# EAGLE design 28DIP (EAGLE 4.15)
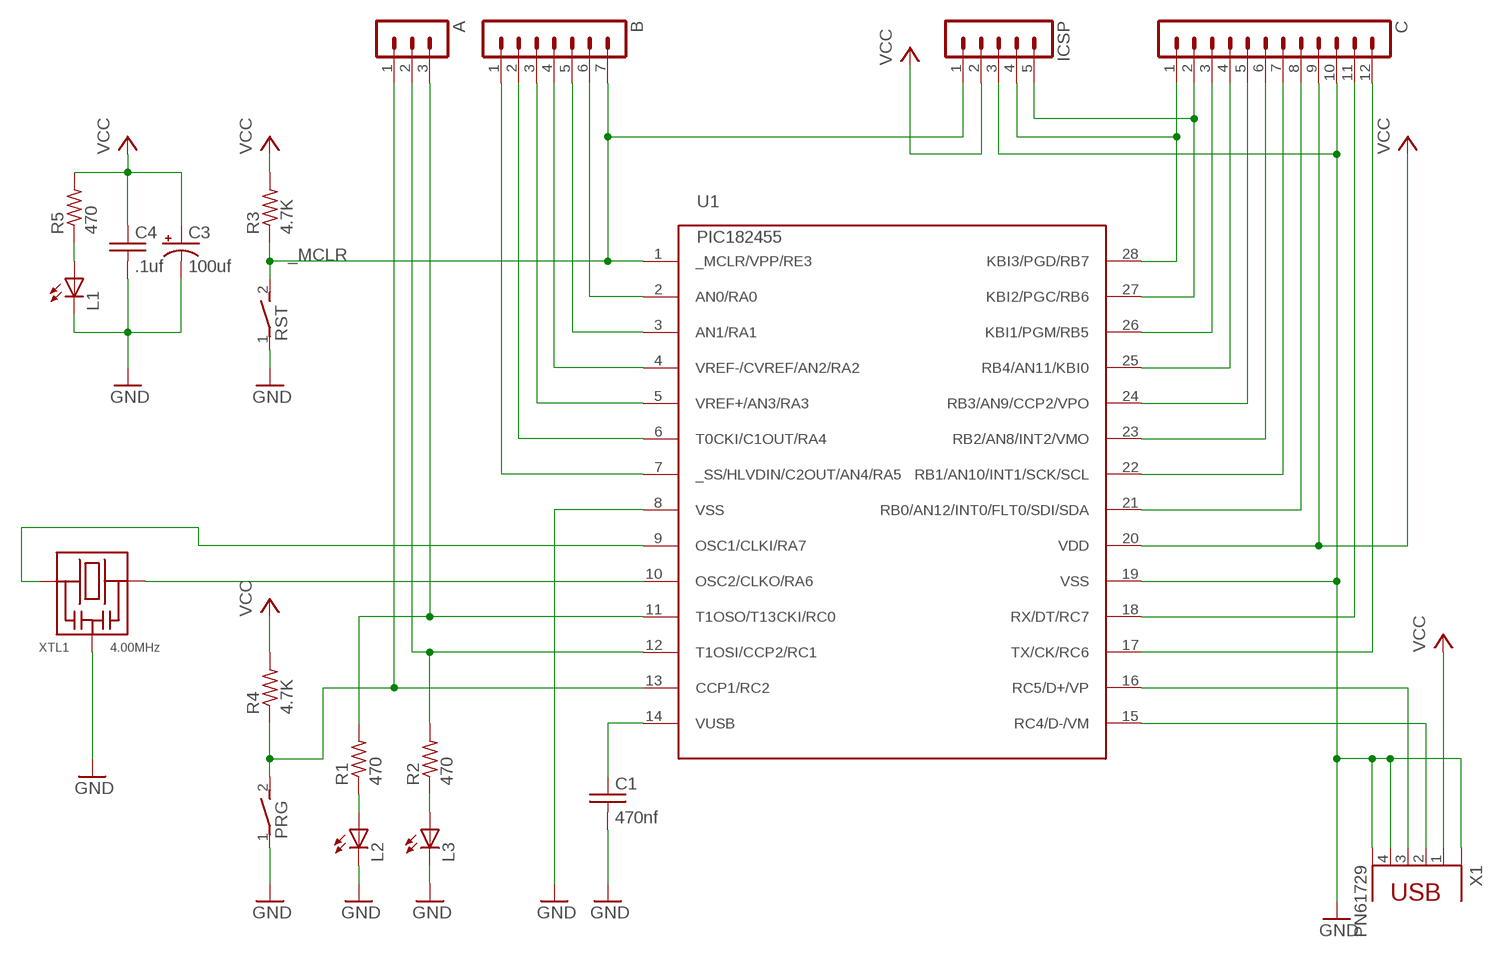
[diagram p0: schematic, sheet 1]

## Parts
A  MA03-1  [MA03-1]
B  MA07-1  [MA07-1]
C  MA12-1  [MA12-1]
C1  470nf  CAPCAP_0200  [CAP_0200]
C3  100uf  CAP_ELECTROLYTICCAP_0200ELECTROLYTIC_0250  [CAP_0200ELECTROLYTIC_0250]
C4  .1uf  CAPCAP_0100  [CAP_0100]
ICSP  MA05-1  [MA05-1]
L1  LED  [LED5MM]
L2  LED  [LED5MM]
L3  LED  [LED5MM]
PRG  SWITCH  [SWITCH]
R1  470  RESISTORRESISTOR_0200FLAT  [RESISTOR_0200FLAT]
R2  470  RESISTORRESISTOR_0200FLAT  [RESISTOR_0200FLAT]
R3  4.7K  RESISTORRESISTOR_0100UP  [RESISTOR_0100UP]
R4  4.7K  RESISTORRESISTOR_0400FLAT  [RESISTOR_0400FLAT]
R5  470  RESISTORRESISTOR_0200FLAT  [RESISTOR_0200FLAT]
RST  SWITCH  [SWITCH]
U1  PIC182455  [DIL28-3]
X1  PN61729  [PN61729]
XTL1  4.00MHz  RESONATOR  [RESONATOR]

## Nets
_MCLR: B.7 ICSP.1 R3.1 RST.2 U1.1(_MCLR/VPP/RE3)
GND: C1.2 C3.- C4.2 C.10 ICSP.3 L1.K(C) L2.K(C) L3.K(C) PRG.1 RST.1 U1.8(VSS) U1.19(VSS) X1.4 X1.GND1(G1) X1.GND2(G2) XTL1.P$1(GND)
N$1: U1.16(RC5/D+/VP) X1.3
N$4: U1.15(RC4/D-/VM) X1.2
N$5: C1.1 U1.14(VUSB)
N$6: L2.A R1.1
N$7: A.1 PRG.2 R4.1 U1.13(CCP1/RC2)
N$8: L3.A R2.1
N$9: L1.A R5.1
N$10: A.3 R1.2 U1.11(T1OSO/T13CKI/RC0)
N$11: A.2 R2.2 U1.12(T1OSI/CCP2/RC1)
N$12: C.1 ICSP.4 U1.28(KBI3/PGD/RB7)
N$13: C.2 ICSP.5 U1.27(KBI2/PGC/RB6)
N$14: C.3 U1.26(KBI1/PGM/RB5)
N$15: C.4 U1.25(RB4/AN11/KBI0)
N$16: C.5 U1.24(RB3/AN9/CCP2/VPO)
N$17: C.6 U1.23(RB2/AN8/INT2/VMO)
N$18: C.7 U1.22(RB1/AN10/INT1/SCK/SCL)
N$19: C.8 U1.21(RB0/AN12/INT0/FLT0/SDI/SDA)
N$20: B.6 U1.2(AN0/RA0)
N$21: B.5 U1.3(AN1/RA1)
N$22: B.4 U1.4(VREF-/CVREF/AN2/RA2)
N$23: B.3 U1.5(VREF+/AN3/RA3)
N$24: B.2 U1.6(T0CKI/C1OUT/RA4)
N$25: B.1 U1.7(_SS/HLVDIN/C2OUT/AN4/RA5)
N$26: C.12 U1.17(TX/CK/RC6)
N$27: C.11 U1.18(RX/DT/RC7)
N$28: U1.10(OSC2/CLKO/RA6) XTL1.P$2
N$31: U1.9(OSC1/CLKI/RA7) XTL1.P$3
VCC: C3.+ C4.1 C.9 ICSP.2 R3.2 R4.2 R5.2 U1.20(VDD) X1.1

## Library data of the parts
A = UBW:MA03-1: PIN HEADER
B = UBW:MA07-1: PIN HEADER
C = UBW:MA12-1: PIN HEADER
C1 C4 = UBW:CAP
C3 = UBW:CAP_ELECTROLYTIC
ICSP = UBW:MA05-1: PIN HEADER
L1-L3 = UBW:LED
PRG RST = UBW:SWITCH: DIL/CODE SWITCH
R1-R5 = UBW:RESISTOR
U1 = UBW:PIC18*2455
X1 = UBW:PN61729: BERG USB connector
XTL1 = UBW:RESONATOR

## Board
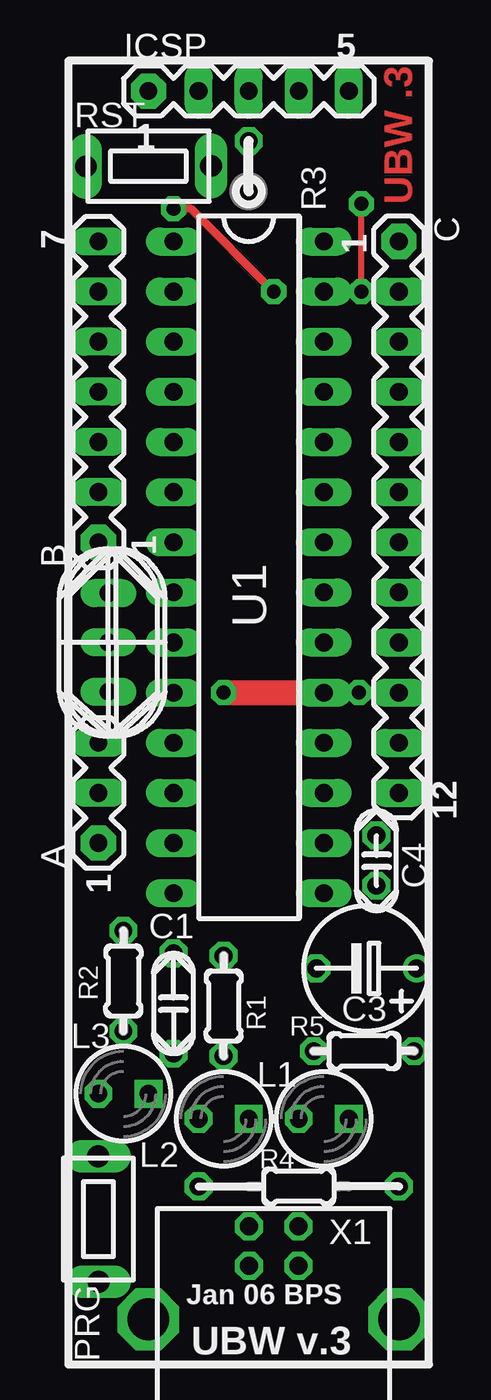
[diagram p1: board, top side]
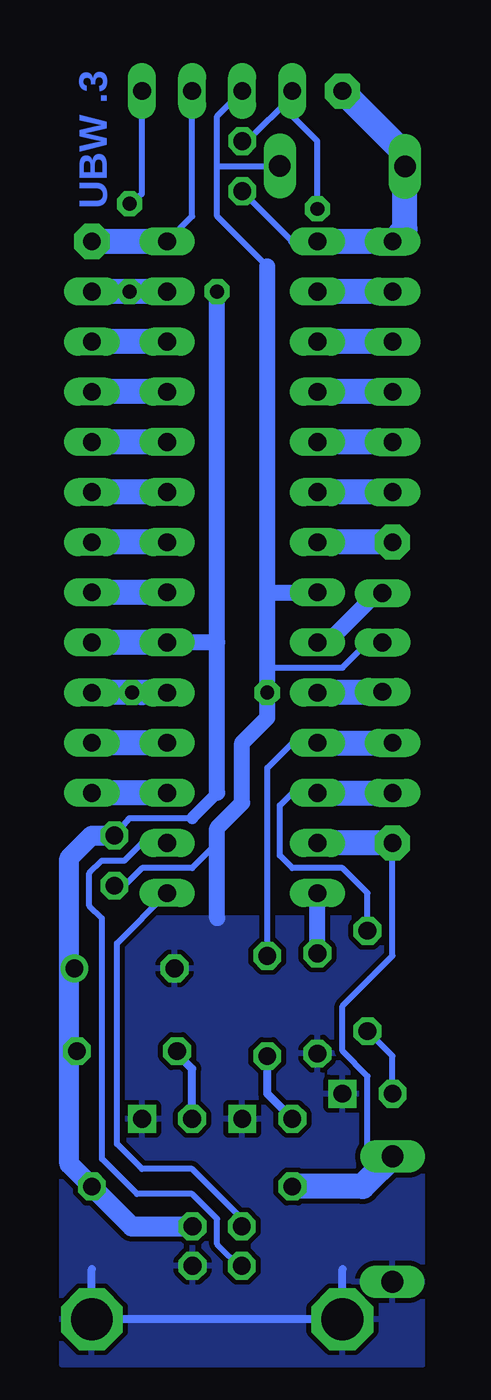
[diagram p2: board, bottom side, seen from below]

No outline drawn. Coordinates in mm, seen from the top.
Copper layers (1*16): Top 0.035mm / dielectric 1.5mm / Bottom 0.035mm
Design rules "New Text Document": minimum track width 10mil, minimum drill 24mil, track to track 10mil, track to pad 10mil, pad to pad 10mil, via to via 10mil, smd to smd 10mil, copper to edge 40mil, drill to drill 10mil, minimum pad ring 10mil, minimum via ring 8mil, stop-mask expansion 0mil, vias tented up to drill 0mil, thermal gap 10mil

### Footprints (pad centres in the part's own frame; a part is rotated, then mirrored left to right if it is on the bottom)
MA03-1 = drill 0.9 pad 1.778 octagon: 1 -2.54,0 | drill 0.9 long: 2 0,0; 3 2.54,0
MA07-1 = drill 0.9 pad 1.778 octagon: 1 -7.62,0 | drill 0.9 long: 2 -5.08,0; 3 -2.54,0; 4 0,0; 5 2.54,0; 6 5.08,0; 7 7.62,0
MA12-1 = drill 0.9 pad 1.778 octagon: 1 -13.97,0 | drill 0.9 long: 2 -11.43,0; 3 -8.89,0; 4 -6.35,0; 5 -3.81,0; 6 -1.27,0; 7 1.27,0; 8 3.81,0; 9 6.35,0; 10 8.89,0; 11 11.43,0; 12 13.97,0
CAP_0200 = drill 0.9 octagon: 1 -2.54,0; 2 2.54,0
CAP_0200ELECTROLYTIC_0250 = drill 0.9 round: + -2.54,0 | drill 0.9 octagon: - 2.54,0
CAP_0100 = drill 0.9 octagon: 1 -1.27,0; 2 1.27,0
MA05-1 = drill 0.9 pad 1.778 octagon: 1 -5.08,0 | drill 0.9 long: 2 -2.54,0; 3 0,0; 4 2.54,0; 5 5.08,0
LED5MM = drill 0.9 octagon: A -1.27,0 | drill 0.9 square: K 1.27,0
SWITCH = drill 1.1 long: 1 0.011,-3.175; 2 -0.011,3.175
RESISTOR_0200FLAT = drill 0.9 octagon: 1 -2.54,0; 2 2.54,0
RESISTOR_0100UP = drill 0.9 octagon: 1 -1.27,0; 2 1.27,0
RESISTOR_0400FLAT = drill 0.9 octagon: 1 -5.08,0; 2 5.08,0
DIL28-3 = drill 0.9 long: 1 -16.51,-3.81; 2 -13.97,-3.81; 3 -11.43,-3.81; 4 -8.89,-3.81; 5 -6.35,-3.81; 6 -3.81,-3.81; 7 -1.27,-3.81; 8 1.27,-3.81; 9 3.81,-3.81; 10 6.35,-3.81; 11 8.89,-3.81; 12 11.43,-3.81; 13 13.97,-3.81; 14 16.51,-3.81; 15 16.51,3.81; 16 13.97,3.81; 17 11.43,3.81; 18 8.89,3.81; 19 6.35,3.81; 20 3.81,3.81; 21 1.27,3.81; 22 -1.27,3.81; 23 -3.81,3.81; 24 -6.35,3.81; 25 -8.89,3.81; 26 -11.43,3.81; 27 -13.97,3.81; 28 -16.51,3.81
PN61729 = drill 0.9 octagon: 1 1.25,4.71; 2 -1.25,4.71; 3 -1.25,2.71; 4 1.25,2.71 | drill 2.108 octagon: GND1 -6.35,0; GND2 6.35,0
RESONATOR = drill 0.9 pad 1.27 long: P$1 0,0; P$2 0,2.5; P$3 0,-2.5

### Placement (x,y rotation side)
A  2.54,29.21 90 top
B  2.54,49.53 90 top
C  17.78,43.18 270 top
C1  6.35,18.54 270 top
C3  16.13,20.32 180 top
C4  16.64,25.78 270 top
ICSP  10.16,64.77 0 top
L1  13.97,12.7 0 top
L2  8.89,12.7 0 top
L3  3.81,13.97 0 top
PRG  2.54,7.62 0 top
R1  8.89,18.41 90 top
R2  3.81,19.68 90 top
R3  10.16,60.96 90 top
R4  12.7,9.27 0 top
R5  16,16.13 0 top
RST  5.08,60.96 90 top
U1  10.16,40.64 270 top
X1  11.43,2.54 0 top
XTL1  3.05,36.83 180 top

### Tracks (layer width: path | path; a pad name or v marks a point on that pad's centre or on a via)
_MCLR
  Bottom 0.305: 7.62,57.15 R3.1
  Bottom 0.406: U1.1 7.62,57.15
  Bottom 1.27: ICSP.1 1.91,61.59 RST.2 1.91,57.78 B.7 U1.1
GND  (via drill 0.7 pad 1.27)
  Top 1.27: v8.89,34.29 U1.19
  Bottom 0.305: 3.81,36.83 5.08,35.56 8.89,35.56 | 11.43,27.43 11.43,26.67 12.7,25.4 15.24,25.4 16.13,24.51 C4.2 | 11.43,60.96 RST.1 | 8.89,55.88 11.43,58.42 11.43,60.96 | 11.43,60.96 11.43,63.5 ICSP.3
  Bottom 0.406: 5.08,5.08 X1.GND1 X1.GND2 17.78,5.08
  Bottom 0.813: 8.89,39.37 8.89,35.56 v8.89,34.29 8.89,33.02 10.16,31.75 10.16,28.7 11.43,27.43 11.43,22.86 | 8.89,39.37 U1.8 | 3.81,36.83 XTL1.P$1 | 8.89,39.37 8.89,55.88
  Bottom 1.27: U1.19 15.24,34.29 | 15.24,34.29 v15.75,34.29 | 15.24,34.29 C.10
  pour Bottom: 1.02,0.25 1.02,22.86 19.3,22.86 19.3,0.25
N$1
  Bottom 0.305: U1.16 15.24,26.67 16.13,25.78 17.27,25.78 17.91,25.15 17.91,23.5 17.27,22.86 17.27,10.67 15.49,8.89 12.7,8.89 11.43,7.62 11.43,6.35 10.18,5.1 | 10.18,5.1 10.16,5.08 | X1.3 10.18,5.1
N$4
  Bottom 0.305: U1.15 16.51,21.59 16.51,11.43 15.24,10.16 12.7,10.16 10.16,7.62 10.18,7.6 X1.2
N$5
  Bottom 0.813: C1.1 U1.14
N$6
  Bottom 0.406: L2.A 8.89,13.97 R1.1
N$7
  Bottom 0.305: 4.06,9.27 4.06,9.91 3.81,10.16 3.81,14.86 5.08,16.13 5.08,18.41 2.54,20.95 A.1
  Bottom 1.27: PRG.2 4.06,9.27 R4.1 | A.1 U1.13
N$8
  Bottom 0.305: L3.A 2.54,15.88 R2.1
N$9
  Bottom 0.406: R5.1 13.46,16 12.7,15.24 L1.A
N$10
  Bottom 0.305: U1.11 7.62,31.75 8.89,30.48 R1.2
  Bottom 1.27: U1.11 A.3
N$11
  Bottom 0.305: U1.12 7.62,29.21 8.26,28.57 8.26,26.04 7.62,25.4 5.08,25.4 3.81,24.13 R2.2
  Bottom 1.27: U1.12 A.2
N$12
  Bottom 0.305: U1.28 12.7,58.42 ICSP.4
  Bottom 1.27: U1.28 C.1
N$13  (via drill 0.7 pad 1.27)
  Top 0.305: v15.88,54.61 v15.88,59.05
  Bottom 0.305: v15.88,59.05 15.24,59.56 ICSP.5
  Bottom 1.27: v15.88,54.61 U1.27 C.2
N$14
  Bottom 1.27: U1.26 C.3
N$15
  Bottom 1.27: U1.25 C.4
N$16
  Bottom 1.27: U1.24 C.5
N$17
  Bottom 1.27: U1.23 C.6
N$18
  Bottom 1.27: U1.22 C.7
N$19
  Bottom 1.27: U1.21 C.8
N$20
  Bottom 1.27: B.6 U1.2
N$21
  Bottom 1.27: B.5 U1.3
N$22
  Bottom 1.27: B.4 U1.4
N$23
  Bottom 1.27: B.3 U1.5
N$24
  Bottom 1.27: B.2 U1.6
N$25
  Bottom 1.27: B.1 U1.7
N$26
  Bottom 1.27: U1.17 C.12
N$27
  Bottom 1.27: U1.18 C.11
N$28
  Bottom 0.813: 3.81,34.29 3.3,34.29
  Bottom 1.27: XTL1.P$2 3.81,34.29 U1.10
N$31
  Bottom 0.813: XTL1.P$3 3.3,39.37 5.84,36.83 U1.9
VCC  (via drill 0.7 pad 1.27)
  Top 0.406: v11.43,54.61 7.24,58.8 v6.35,58.8
  Bottom 0.305: 12.7,27.94 15.88,27.94 C4.1 | v6.35,58.8 6.35,62.23 7.62,63.5 7.62,64.52 | 7.62,64.52 9.91,62.23 R3.2 | 18.92,16 18.54,16 R5.2 | 7.62,64.52 ICSP.2
  Bottom 0.406: 18.92,20.32 C3.+ | 12.7,7.24 X1.1
  Bottom 0.61: 12.7,27.94 11.43,29.21
  Bottom 0.813: 11.43,29.21 11.43,36.83 | 11.43,36.83 U1.20 | 11.43,36.83 v11.43,54.61
  Bottom 1.016: C4.1 17.78,27.05 18.92,25.91 18.92,20.32 18.92,16 18.92,10.41 R4.2 15.75,7.24 12.7,7.24
  Bottom 1.27: U1.20 C.9

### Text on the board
Top: UBW .3
Bottom: UBW .3
tPlace: Jan 06 BPS | UBW v.3
tNames: ICSP | 5 | 5 | 1 | 1 | 1 | 1 | C | 7 | 7 | B | 1 | 1 | 12 | 12 | A | 1 | 1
